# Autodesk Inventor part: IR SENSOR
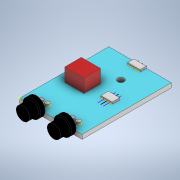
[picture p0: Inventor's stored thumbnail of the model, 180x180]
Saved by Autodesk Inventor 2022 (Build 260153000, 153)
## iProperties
Created: 2021-06
Part Number: IR SENSOR
Material: Generic
Document SubType Name: Sheet Metal
Designer: USER
Density: 1 g/cm^3
Sheet Metal Rule: Default_mm
Appearance: Default
Author: USER
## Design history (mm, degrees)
node "Face1"
  sketch "Sketch1"
    geometry: L1 (0, 0)-(-7, 0); L2 (-7, 0)-(-7, -10); L3 (-7, -10)-(0, -10); L4 (0, -10)-(0, 0)
    constraints: 8 end point, 2 parallel, 1 horizontal, 1 perpendicular
    dimensions: "d0" = 7 distance of L3.end L2.end; "d1" = 10 distance of L2.end L1.end
sketch "Sketch2"
  geometry: L1 (7, 10)-(0, 10) reference; L2 (2.8, 10)-(4.2, 10); L3 (4.2, 10)-(4.2, 9.3); L4 (4.2, 9.3)-(2.8, 9.3); L5 (2.8, 9.3)-(2.8, 10); L6 (0, 0)-(0, 10) reference; L7 (0.429, 3.846)-(2.305, 3.846); L8 (2.305, 3.846)-(2.305, 6.403); L9 (2.305, 6.403)-(0.429, 6.403); L10 (0.429, 6.403)-(0.429, 3.846); L11 (4.496, 4.593)-(5.774, 4.593); L12 (5.774, 4.593)-(5.774, 5.456); L13 (5.774, 5.456)-(4.496, 5.456); L14 (4.496, 5.456)-(4.496, 4.593); L15 (7, 10)-(7, 0) reference; C1 r 0.25 at (1.5, 0.908); C2 r 0.25 at (2.2, 0.908); C3 r 0.25 at (4.994, 0.908); C4 r 0.25 at (5.694, 0.908)
  constraints: 24 end point, 5 perpendicular, 4 centre point, 4 parallel, 2 horizontal, 2 point on line
  dimensions: "d3" = 1.4 distance of L2.start L2.end; "d4" = 0.7 distance of L2.end L3.end; "d5" = 2.8 distance between parallel lines of L5 L6; "d6" = 0.5 diameter of C1; "d7" = 0.5 diameter of C2; "d8" = 0.5 diameter of C3; "d9" = 0.5 diameter of C4; "d10" = 0.7 distance of C2.centre C1.centre; "d11" = 0.7 distance of C4.centre C3.centre; "d12" = 1.5 distance from line of C1.centre L6; "d13" = 1.3061 distance from line of L15 C4.centre
extrude "Extrusion1" join sketch "Sketch2" distance "d14" = 0.2; taper "d15" = 0 deg
sketch "Sketch3"
  geometry: 1 further point
sketch "Sketch4"
  geometry: L1 (0.992, 5.926)-(3.154, 5.926); L2 (3.154, 5.926)-(3.154, 4.064); L3 (3.154, 4.064)-(0.992, 4.064); L4 (0.992, 4.064)-(0.992, 5.926); 1 further point
  constraints: 8 end point, 2 parallel, 1 horizontal, 1 perpendicular
extrude "Extrusion2" join sketch "Sketch4" distance "d16" = 1.5; taper "d17" = 0 deg
sketch "Sketch5"
  geometry: 1 further point
sketch "Sketch6"
  geometry: C1 r 1 at (1.865, 0.7); C2 r 1 at (5.34, 0.7); 1 further point
  constraints: 2 centre point
  dimensions: "d18" = 2 diameter of C1; "d19" = 2 diameter of C2
extrude "Extrusion3" join sketch "Sketch6" distance "d20" = 0.5; taper "d21" = 0 deg
sketch "Sketch7"
  geometry: C1 r 0.75 at (1.865, 0.7); C2 r 0.75 at (5.34, 0.7); A1 r 1 centre (1.865, 0.7) between (2.845, 0.5) and (0.885, 0.5) reference; A2 r 1 centre (5.34, 0.7) between (6.32, 0.5) and (4.36, 0.5) reference; 1 further point
  constraints: 2 centre point, 2 coincident
  dimensions: "d22" = 1.5 diameter of C1; "d23" = 1.5 diameter of C2
extrude "Extrusion4" join sketch "Sketch7" distance "d24" = 1.5; taper "d25" = 0 deg
sketch "Sketch8"
  geometry: L1 (1.5, 0.908)-(1.5, 0); L2 (2.2, 0.908)-(2.2, 0); L3 (4.986, 0.908)-(4.986, 0); L4 (5.694, 0.908)-(5.694, 0); L5 (4.626, 0)-(6.054, 0) reference; L6 (4.496, 5.456)-(5.774, 5.456) reference; L7 (4.808, 5.456)-(4.808, 5.937); L8 (5.135, 5.456)-(5.135, 5.937); L9 (5.444, 5.456)-(5.444, 5.937); L10 (5.774, 4.593)-(4.496, 4.593) reference; L11 (4.808, 4.593)-(4.808, 3.926); L12 (5.135, 4.593)-(5.135, 3.926); L13 (5.444, 4.593)-(5.444, 3.926); C1 r 0.25 at (1.5, 0.908) reference; C2 r 0.25 at (2.2, 0.908) reference; C3 r 0.25 at (5.694, 0.908) reference; 1 further point
  constraints: 20 end point, 10 vertical, 5 point on line, 2 midpoint
sketch "Sketch9"
  geometry: L1 (4.2, 9.3)-(2.8, 9.3) reference; L2 (3.026, 9.3)-(3.026, 10.279); L3 (3.5, 9.3)-(3.5, 10.279); L4 (3.975, 9.3)-(3.975, 10.279); 1 further point
  constraints: 6 end point, 3 vertical, 2 point on line, 1 midpoint
sketch "Sketch10"
  geometry: 1 further point
sketch "Sketch11"
  geometry: C1 r 0.395 at (2.073, 5.037); C2 r 0.364 at (3.909, 7.439); 1 further point
  constraints: 2 centre point
extrude "Extrusion5" cut sketch "Sketch11" extent not by distance; stored distance "d26" = 0; taper "d27" = 0 deg
body "Solid1"
face "Plate1" dims "d2" = 0.5 (= Thickness)
other parameters: "Thickness" = 0.5, "BendRadius" = 0.5 (= Thickness), "BendReliefWidth" = 0.5 (= Thickness), "BendReliefDepth" = 0.25 (= 0.5 x Thickness), "CornerReliefSize" = 2 (= 4 x Thickness), "SeamGap" = 0.01, "MinimumRemnant" = 1 (= 2 x Thickness), "TransitionRadius" = 0.5 (= BendRadius), "JacobiRadiusSize" = 0.5 (= BendRadius), "GapSize" = 0.5 (= Thickness)
